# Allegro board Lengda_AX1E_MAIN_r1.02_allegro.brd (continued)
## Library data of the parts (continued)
PR4 PR14 PR15 PR36 PR39 PR41 PR47 PR73 R1 R6 R7 R17 R22 R26 R38 R42 R73 R92 R97 R98 R104 R106 R107 R109 R114 R122-R124 R127 R146-R149 R159 R169 R170 R176 R178 R180 R193 R196 R203 R222 R250 R266 R270 R277 R278 R283 R311 R312 R323 R324 R332 R333 R336 R341 R343 R346 R347 R358 R364 R366 R367 R376 R379 R395 R399 R409 R410 R438 R446 R506 R521 R537-R539 R543 R551 R556 R560 R561 R567 R568 R622 R624 R730 R732 R791 R796 R797 R800 R815 R860 R862 R865-R868 R874 R876 R917 R920 R926 R930 R932 = R: alternate symbols: (T:RC0603N;B:RC0603M)
PU3 = 8+1_RT9610CQW_0
Q1 Q2 Q4 Q11 Q18 Q40 = NMOS-GSD: alternate symbols: (T:SOT95P280-3N;B:SOT95P280-3M)
Q5 Q6 Q8 Q9 Q22 Q23 Q29 Q32 Q56 Q68 Q74 = PWR_N_MOSFET
Q7 Q10 Q15 Q30 Q31 Q69 Q71 Q76-Q81 Q83-Q86 Q88 = NMOS-GSD: alternate symbols: (T:SOT95P240-3N;B:SOT95P240-3M)
Q12 Q13 Q44 = NMOS-GSD_0
Q14 Q41 Q42 = NMOS-GSD
Q17 = PWR_P_MOSFET_1
Q19 Q27 = NMOS-GSD: signal model: NMOS-GSD_SOT95P240-3N_2N7002L_1_2N7002LT1
Q34 = 3_APM1110NU
Q36 Q72 = NPN-BEC+2R: alternate symbols: (T:SOT65P210-3N;B:SOT65P210-3M)
Q48 = FET_NMOS_0
Q49 = 2021390400
R4 R13 R14 R43 R45 R48 R56 R62 R71 R81 R87 R145 R150 R158 R161 R164 R166 R174 R182 R183 R190-R192 R197 R215 R218 R221 R223 R232 R234 R243-R245 R263 R264 R273-R275 R281 R331 R337 R362 R363 R371 R380 R385 R386 R421 R422 R426 R439 R462 R465 R478 R482 R485 R490 R492 R493 R501-R504 R509-R511 R514-R516 R522 R525 R526 R535 R542 R545 R572 R578-R580 R584-R587 R609 R610 R788-R790 R793 R795 R802 R803 R811 R816 R828 R833 R834 R877-R881 R883 R884 R886 R887 R890 R891 R893 R901 R902 R910 R918 R927 R928 R1392 = R_0
R11 R24 R126 R130 R319 R320 R334 R344 R368 R394 R406 R432 = R: signal model: R_RC0402N_0_0
R84 = R: signal model: R_RC0402N_10_10
R201 = R: signal model: R_0_RC0402N_0_0
R261 = R: alternate symbols: (T:RC1206N;B:RC1206M)
R314 R315 R448 R450-R457 R477 R479 R483 R484 R489 = R: signal model: R_RC0603N_0_0
R407 = R: signal model: R_RC0402N_22_22
R428-R431 R480 R481 R488 R491 = R: signal model: R_RC0603N_0_F_0_F
R449 = R_0: signal model: R_RC0603N_0_0
R463 R464 = R_0: signal model: R_0_RC0402N_0_0
R494-R500 R505 = R_0: signal model: R_0_RC0603N_0_0
R573 R574 = R: alternate symbols: (T:RC0805N;B:RC0805M)
R1388 = R_4
SW1 = SW-2+2
TP1 TP3 TP6-TP11 TP14 TP15 TP18 TP26-TP59 TP63 TP65 TP66 TP69-TP73 = TP
TP12 TP13 TP16 TP17 TP19 TP20 TP22 TP23 = PAD_1: room: CPU
TP21 TP24 TP25 = TP#2: room: TEST_POINT
U1 = 1526_ICLU_LP5366
U2 = 20+1_RT8231AB
U3 = 40+1_RT3613EB
U4 U14 = 5_APL3512
U5 U10 U18 U23 U32 U35 U40 U54 U56 U57 = 5_SN74LVC1G08DCKR
U6 = 20+1_RT6543A
U7 U20 U24 = 12_RT6228XGQUF
U9 = 128_IT5570_2
U11 U22 U27 U29 U41 = 5_APL3511
U13 U50 = 5_SN74LVC1G07DCK
U15 U16 U21 U39 U55 = 8+1_TPS22965
U25 = 48+1_ALC256
U30 = 32+1_RTL8111H
U31 = 24_EG24A005S
U33 = 5_SN74AHC1G09DCK
U34 = 5_SN74LVC1G06DCK
U36 = 8_MX25L4005AMC-12G
U36_S U49_1 = SPI_FLASH_3: Tolerance: #TOL; User Part Number: HAMP; room: EC
U37 = 16+1_APW7228BRI
U38 = 3_APL3517
U42 = 56+1_PS8625QFN56G
U43 U44 = 8_AT24C02A
U49 = 8_W25Q64FV
U51 = 10+1_APW8804QB_0
U52 = APL591X_1
UC1 = C: alternate symbols: (T:CC0805N;B:CC0805M)
X1 X2 = OSC-4_7
X4 = CRYSTAL

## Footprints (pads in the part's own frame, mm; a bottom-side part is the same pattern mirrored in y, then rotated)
BGA91P35X99_1526N
  round 0.356 smd: A3(10.767,-24.365) A48(-11.405,-24.365) A49(-11.865,-23.905) B2(11.309,-23.816) C1(11.865,-23.255) DW1(11.865,23.905) DW2(11.405,24.365) DW48(-11.405,24.365) DW49(-11.865,23.905)
  round 0.33 smd: A4(10.117,-24.365) A47(-10.755,-24.365) B3(10.666,-23.723) B48(-11.237,-23.737) C2(11.22,-23.172) C49(-11.865,-23.255) D1(11.865,-22.605) DE12(6.31,17.032) DE13(5.48,17.032) DE15(4.65,17.032) DE17(3.82,17.032) DE18(2.99,17.032) DE20(2.16,17.032) DE22(1.33,17.032) DE23(0.5,17.032) DE26(-0.33,17.032) DE28(-1.16,17.032) DE29(-1.99,17.032) DE31(-2.82,17.032) DE33(-3.65,17.032) DF12(6.31,17.682) DF13(5.48,17.682) DF15(4.65,17.682) DF17(3.82,17.682) DF18(2.99,17.682) DF20(2.16,17.682) DF22(1.33,17.682) DF23(0.5,17.682) DF26(-0.33,17.682) DF28(-1.16,17.682) DF29(-1.99,17.682) DF31(-2.82,17.682) DF33(-3.65,17.682) DG12(6.31,18.332) DG13(5.48,18.332) DG15(4.65,18.332) DG17(3.82,18.332) DG18(2.99,18.332) DG20(2.16,18.332) DG22(1.33,18.332) DG23(0.5,18.332) DG26(-0.33,18.332) DG28(-1.16,18.332) DG29(-1.99,18.332) DG31(-2.82,18.332) DG33(-3.65,18.332) DU1(11.865,23.255) DU49(-11.865,23.255) DV2(11.237,23.737) DV48(-11.237,23.737) DW3(10.755,24.365) DW47(-10.755,24.365)
  round 0.305 smd: A5(9.467,-24.365) A7(8.658,-24.365) A33(-3.593,-24.365) A43(-8.707,-24.365) A44(-9.455,-24.365) A46(-10.105,-24.365) AA12(6.127,-14.312) AA35(-4.855,-14.311) AA37(-5.778,-14.311) AA45(-9.59,-14.246) AA47(-10.861,-14.246) AB3(10.893,-13.923) AB5(9.905,-13.923) AB6(9.189,-13.855) AB7(8.539,-13.855) AB9(7.889,-13.855) AB10(7.239,-13.855) AB11(6.589,-13.855) AB13(5.665,-13.855) AB34(-4.393,-13.853) AB36(-5.316,-13.853) AB38(-6.24,-13.853) AB39(-6.89,-13.853) AB41(-7.54,-13.853) AB42(-8.19,-13.853) AB43(-8.84,-13.853) AB45(-9.915,-13.626) AB47(-10.565,-13.626) AC3(10.565,-13.249) AC5(9.915,-13.249) AC12(6.127,-13.397) AC35(-4.855,-13.396) AC37(-5.778,-13.396) AC45(-9.59,-12.995) AC46(-10.241,-12.995) AD3(10.89,-12.686) AD4(10.24,-12.686) AD6(9.189,-12.94) AD7(8.539,-12.94) AD9(7.889,-12.94) AD10(7.239,-12.94) AD11(6.589,-12.94) AD34(-4.393,-12.938) AD35(-4.855,-12.481) AD36(-5.316,-12.938) AD37(-5.778,-12.481) AD38(-6.24,-12.938) AD39(-6.89,-12.938) AD41(-7.54,-12.938) AD42(-8.19,-12.938) AD43(-8.84,-12.938) AE3(10.565,-12.123) AE5(9.915,-12.123) AE6(9.189,-12.025) AE7(8.539,-12.025) AE9(7.889,-12.025) AE11(6.965,-12.025) AE36(-5.316,-12.023) AE38(-6.24,-12.023) AE39(-6.89,-12.023) AE41(-7.54,-12.023) AE42(-8.19,-12.023) AE43(-8.84,-12.023) AE45(-9.915,-12.364) AE47(-10.565,-12.364) AF10(7.427,-11.567) AF37(-5.778,-11.566) AF45(-9.59,-11.744) AF47(-10.861,-11.744) AG3(10.893,-11.449) AG5(9.905,-11.449) AG6(9.189,-11.11) AG7(8.539,-11.11) AG9(7.889,-11.11) AG11(6.965,-11.11) AG36(-5.316,-11.108) AG38(-6.24,-11.108) AG39(-6.89,-11.108) AG41(-7.54,-11.108) AG42(-8.19,-11.108) AG43(-8.84,-11.108) AG45(-9.915,-11.124) AG47(-10.565,-11.124) AH10(7.427,-10.652) AH37(-5.778,-10.651) AH45(-9.59,-10.493) AH46(-10.241,-10.493) AJ3(10.489,-10.195) AJ5(9.839,-10.195) AJ6(9.189,-10.195) AJ7(8.539,-10.195) AJ9(7.889,-10.195) AJ11(6.965,-10.195) AJ36(-5.316,-10.193) AJ38(-6.24,-10.193) AJ39(-6.89,-10.193) AJ41(-7.54,-10.193) AJ42(-8.19,-10.193) AJ43(-8.84,-10.193) AK10(7.427,-9.737) AK37(-5.778,-9.736) AK45(-9.915,-9.862) AK47(-10.565,-9.862) AL3(10.489,-9.28) AL5(9.839,-9.28) AL6(9.189,-9.28) AL7(8.539,-9.28) AL9(7.889,-9.28) AL11(6.965,-9.28) AL36(-5.316,-9.278) AL38(-6.24,-9.278) AL39(-6.89,-9.278) AL41(-7.54,-9.278) AL42(-8.19,-9.278) AL43(-8.84,-9.278) AL45(-9.59,-9.242) AL47(-10.861,-9.242) AM10(7.427,-8.822) AM37(-5.778,-8.821) AM45(-9.915,-8.622) AM47(-10.565,-8.622) AN3(10.489,-8.365) AN5(9.839,-8.365) AN6(9.189,-8.365) AN7(8.539,-8.365) AN9(7.889,-8.365) AN11(6.965,-8.365) AN36(-5.316,-8.363) AN38(-6.24,-8.363) AN39(-6.89,-8.363) AN41(-7.54,-8.363) AN42(-8.19,-8.363) AN43(-8.84,-8.363) AN45(-9.59,-7.991) AN46(-10.241,-7.991) AP10(7.427,-7.907) AP37(-5.778,-7.906) AR3(10.489,-7.45) AR5(9.839,-7.45) AR6(9.189,-7.45) AR7(8.539,-7.45) AR9(7.889,-7.45) AR10(7.427,-6.992) AR11(6.965,-7.45) AR36(-5.316,-7.448) AR37(-5.778,-6.991) AR38(-6.24,-7.448) AR39(-6.89,-7.448) AR41(-7.54,-7.448) AR42(-8.19,-7.448) AR43(-8.84,-7.448) AR45(-9.915,-7.36) AR47(-10.565,-7.36) AT3(10.489,-6.535) AT5(9.839,-6.535) AT6(9.189,-6.535) AT7(8.539,-6.535) AT9(7.889,-6.535) AT11(6.965,-6.535) AT36(-5.316,-6.533) AT38(-6.24,-6.533) AT39(-6.89,-6.533) AT41(-7.54,-6.533) AT42(-8.19,-6.533) AT43(-8.84,-6.533) AT45(-9.59,-6.74) AT47(-10.861,-6.74) AU10(7.427,-6.077) AU37(-5.778,-6.076) AU45(-9.915,-6.12) AU47(-10.565,-6.12) AV3(10.489,-5.62) AV5(9.839,-5.62) AV6(9.189,-5.62) AV7(8.539,-5.62) AV9(7.889,-5.62) AV11(6.965,-5.62) AV36(-5.316,-5.618) AV38(-6.24,-5.618) AV39(-6.89,-5.618) AV41(-7.54,-5.618) AV42(-8.19,-5.618) AV43(-8.84,-5.618) AV45(-9.59,-5.489) AV46(-10.241,-5.489) AW10(7.427,-5.162) AW37(-5.778,-5.161) AY3(10.489,-4.705) AY5(9.839,-4.705) AY6(9.189,-4.705) AY7(8.539,-4.705) AY9(7.889,-4.705) AY11(6.965,-4.705) AY36(-5.316,-4.703) AY38(-6.24,-4.703) AY39(-6.89,-4.703) AY41(-7.54,-4.703) AY42(-8.19,-4.703) AY43(-8.84,-4.703) AY45(-9.915,-4.858) AY47(-10.565,-4.858) B4(10.016,-23.723) B7(8.658,-23.715) B33(-3.593,-23.715) B43(-8.707,-23.715) B45(-9.956,-23.577) B47(-10.587,-23.737) BA10(7.427,-4.247) BA37(-5.778,-4.246) BA45(-9.59,-4.238) BA47(-10.861,-4.238) BB3(10.489,-3.79) BB5(9.839,-3.79) BB6(9.189,-3.79) BB7(8.539,-3.79) BB9(7.889,-3.79) BB11(6.965,-3.79) BB36(-5.316,-3.788) BB38(-6.24,-3.788) BB39(-6.89,-3.788) BB41(-7.54,-3.788) BB42(-8.19,-3.788) BB43(-8.84,-3.788) BB45(-9.915,-3.618) BB47(-10.565,-3.618) BC10(7.427,-3.332) BC37(-5.778,-3.331) BD3(10.489,-2.875) BD5(9.839,-2.875) BD6(9.189,-2.875) BD7(8.539,-2.875) BD9(7.889,-2.875) BD11(6.965,-2.875) BD36(-5.316,-2.873) BD38(-6.24,-2.873) BD39(-6.89,-2.873) BD41(-7.54,-2.873) BD42(-8.19,-2.873) BD43(-8.84,-2.873) BD45(-9.59,-2.987) BD46(-10.241,-2.987) BE10(7.427,-2.417) BE37(-5.778,-2.416) BE45(-9.915,-2.356) BE47(-10.565,-2.356) BF3(10.489,-1.96) BF5(9.839,-1.96) BF6(9.189,-1.96) BF7(8.539,-1.96) BF9(7.889,-1.96) BF10(7.427,-1.502) BF11(6.965,-1.96) BF36(-5.316,-1.958) BF37(-5.778,-1.501) BF38(-6.24,-1.958) BF39(-6.89,-1.958) BF41(-7.54,-1.958) BF42(-8.19,-1.958) BF43(-8.84,-1.958) BF45(-9.59,-1.736) BF47(-10.861,-1.736) BG3(10.489,-1.045) BG5(9.839,-1.045) BG6(9.189,-1.045) BG7(8.539,-1.045) BG9(7.889,-1.045) BG11(6.965,-1.045) BG36(-5.316,-1.043) BG38(-6.24,-1.043) BG39(-6.89,-1.043) BG41(-7.54,-1.043) BG42(-8.19,-1.043) BG43(-8.84,-1.043) BG45(-9.915,-1.116) BG47(-10.565,-1.116) BH10(7.427,-0.587) BH37(-5.778,-0.586) BJ3(10.489,-0.13) BJ5(9.839,-0.13) BJ6(9.189,-0.13) BJ7(8.539,-0.13) BJ9(7.889,-0.13) BJ11(6.965,-0.13) BJ36(-5.316,-0.128) BJ38(-6.24,-0.128) BJ39(-6.89,-0.128) BJ41(-7.54,-0.128) BJ42(-8.19,-0.128) BJ43(-8.84,-0.128) BJ45(-9.59,-0.485) BJ46(-10.241,-0.485) BL10(7.427,0.328) BL37(-5.778,0.33) BL45(-9.915,0.146) BL47(-10.565,0.146) BM3(10.489,0.786) BM5(9.839,0.786) BM6(9.189,0.786) BM7(8.539,0.786) BM9(7.889,0.786) BM11(6.965,0.786) BM36(-5.316,0.787) BM38(-6.24,0.787) BM39(-6.89,0.787) BM41(-7.54,0.787) BM42(-8.19,0.787) BM43(-8.84,0.787) BM45(-9.59,0.766) BM47(-10.861,0.766) BN10(7.427,1.243) BN37(-5.778,1.245) BN45(-9.915,1.386) BN47(-10.565,1.386) BP3(10.489,1.701) BP5(9.839,1.701) BP6(9.189,1.701) BP7(8.539,1.701) BP9(7.889,1.701) BP11(6.965,1.701) BP36(-5.316,1.702) BP38(-6.24,1.702) BP39(-6.89,1.702) BP41(-7.54,1.702) BP42(-8.19,1.702) BP43(-8.84,1.702) BR10(7.427,2.158) BR37(-5.778,2.16) BR45(-9.59,2.017) BR46(-10.241,2.017) BT3(10.489,2.616) BT5(9.839,2.616) BT6(9.189,2.616) BT7(8.539,2.616) BT9(7.889,2.616) BT11(6.965,2.616) BT36(-5.316,2.617) BT38(-6.24,2.617) BT39(-6.89,2.617) BT41(-7.54,2.617) BT42(-8.19,2.617) BT43(-8.84,2.617) BT45(-9.915,2.648) BT47(-10.565,2.648) BU10(7.427,3.073) BU37(-5.778,3.075) BU45(-9.59,3.268) BU47(-10.861,3.268) BV3(10.489,3.531) BV5(9.839,3.531) BV6(9.189,3.531) BV7(8.539,3.531) BV9(7.889,3.531) BV11(6.965,3.531) BV36(-5.316,3.532) BV38(-6.24,3.532) BV39(-6.89,3.532) BV41(-7.54,3.532) BV42(-8.19,3.532) BV43(-8.84,3.532) BV45(-9.915,3.888) BV47(-10.565,3.888) BW3(10.489,4.446) BW5(9.839,4.446) BW6(9.189,4.446) BW7(8.539,4.446) BW9(7.889,4.446) BW10(7.427,3.988) BW11(6.965,4.446) BW36(-5.316,4.447) BW37(-5.778,3.99) BW38(-6.24,4.447) BW39(-6.89,4.447) BW41(-7.54,4.447) BW42(-8.19,4.447) BW43(-8.84,4.447) BY10(7.427,4.903) BY37(-5.778,4.905) BY45(-9.59,4.519) BY46(-10.241,4.519) C3(10.577,-23.079) C5(9.927,-23.079) C6(9.332,-23.393) C7(8.658,-23.065) C8(8.095,-23.39) C9(7.532,-23.065) C11(6.858,-23.393) C12(6.184,-23.065) C13(5.621,-23.39) C14(5.058,-23.065) C16(4.384,-23.393) C33(-3.593,-23.065) C34(-4.176,-23.361) C35(-4.795,-23.065) C38(-6.077,-23.065) C39(-6.73,-23.361) C40(-7.383,-23.065) C43(-8.707,-23.065) C44(-9.336,-23.359) C47(-10.479,-23.087) C48(-11.234,-23.087) CA3(10.489,5.361) CA5(9.839,5.361) CA6(9.189,5.361) CA7(8.539,5.361) CA9(7.889,5.361) CA11(6.965,5.361) CA36(-5.316,5.362) CA38(-6.24,5.362) CA39(-6.89,5.362) CA41(-7.54,5.362) CA42(-8.19,5.362) CA43(-8.84,5.362) CA45(-9.915,5.15) CA47(-10.565,5.15) CB10(7.427,5.818) CB37(-5.778,5.82) CB45(-9.59,5.77) CB47(-10.861,5.77) CC3(10.893,6.149) CC5(9.905,6.149) CC6(9.189,6.276) CC7(8.539,6.276) CC9(7.889,6.276) CC11(6.965,6.276) CC36(-5.316,6.277) CC38(-6.24,6.277) CC39(-6.89,6.277) CC41(-7.54,6.277) CC42(-8.19,6.277) CC43(-8.84,6.277) CC45(-9.915,6.39) CC47(-10.565,6.39) CD3(10.565,6.823) CD5(9.915,6.823) CD10(7.427,6.733) CE3(10.89,7.386) CE4(10.24,7.386) CE6(9.189,7.191) CE7(8.539,7.191) CE9(7.889,7.191) CE11(6.965,7.191) CE34(-4.29,7.192) CE35(-4.94,7.192) CE37(-5.59,7.192) CE38(-6.24,7.192) CE39(-6.89,7.192) CE41(-7.54,7.192) CE42(-8.19,7.192) CE43(-8.84,7.192) CE45(-9.59,7.021) CE46(-10.241,7.021) CF3(10.565,7.949) CF5(9.915,7.949) CF10(7.427,7.648) CF33(-3.828,7.65) CF45(-9.915,7.652) CF47(-10.565,7.652) CG6(9.189,8.106) CG7(8.539,8.106) CG9(7.889,8.106) CG11(6.965,8.106) CG32(-3.366,8.107) CG34(-4.29,8.107) CG35(-4.94,8.107) CG37(-5.59,8.107) CG38(-6.24,8.107) CG39(-6.89,8.107) CG41(-7.54,8.107) CG42(-8.19,8.107) CG43(-8.84,8.107) CG45(-9.59,8.272) CG47(-10.861,8.272) CH3(10.893,8.623) CH5(9.905,8.623) CH10(7.427,8.563) CH33(-3.828,8.689) CH45(-9.915,8.892) CH47(-10.565,8.892) CJ3(10.565,9.297) CJ5(9.915,9.297) CJ6(9.189,9.021) CJ7(8.539,9.021) CJ9(7.889,9.021) CJ11(6.965,9.021) CJ32(-3.366,9.272) CJ34(-4.29,9.272) CJ35(-4.94,9.272) CJ37(-5.59,9.272) CJ38(-6.24,9.272) CJ39(-6.89,9.272) CJ41(-7.54,9.272) CJ42(-8.19,9.272) CJ43(-8.84,9.272) CK3(10.89,9.86) CK4(10.24,9.86) CK6(9.189,9.936) CK7(8.539,9.936) CK9(7.889,9.936) CK10(7.427,9.478) CK11(6.965,9.936) CK33(-3.828,9.73) CK45(-9.59,9.523) CK46(-10.241,9.523) CL3(10.565,10.423) CL5(9.915,10.423) CL10(7.427,10.393) CL32(-3.366,10.187) CL34(-4.29,10.187) CL35(-4.94,10.187) CL37(-5.59,10.187) CL38(-6.24,10.187) CL39(-6.89,10.187) CL41(-7.54,10.187) CL42(-8.19,10.187) CL43(-8.84,10.187) CL45(-9.915,10.154) CL47(-10.565,10.154) CM6(9.189,10.851) CM7(8.539,10.851) CM9(7.889,10.851) CM11(6.965,10.851) CM33(-3.828,10.645) CM45(-9.59,10.774) CM47(-10.861,10.774) CN3(10.893,11.097) CN5(9.905,11.097) CN10(7.427,11.308) CN32(-3.366,11.102) CN34(-4.29,11.102) CN35(-4.94,11.102) CN37(-5.59,11.102) CN38(-6.24,11.102) CN39(-6.89,11.102) CN41(-7.54,11.102) CN42(-8.19,11.102) CN43(-8.84,11.102) CN45(-9.915,11.394) CN47(-10.565,11.394) CP3(10.565,11.771) CP5(9.915,11.771) CP6(9.189,11.766) CP7(8.539,11.766) CP9(7.889,11.766) CP11(6.965,11.766) CP33(-3.828,11.56) CR3(10.89,12.334) CR4(10.24,12.334) CR10(7.427,12.223) CR32(-3.366,12.017) CR34(-4.29,12.017) CR35(-4.94,12.017) CR37(-5.59,12.017) CR38(-6.24,12.017) CR39(-6.89,12.017) CR41(-7.54,12.017) CR42(-8.19,12.017) CR43(-8.84,12.017) CR45(-9.59,12.025) CR46(-10.241,12.025) CT3(10.565,12.897) CT5(9.915,12.897) CT6(9.189,12.681) CT7(8.539,12.681) CT9(7.889,12.681) CT11(6.965,12.681) CT32(-3.366,12.932) CT33(-3.828,12.475) CT34(-4.29,12.932) CT35(-4.94,12.932) CT37(-5.59,12.932) CT38(-6.24,12.932) CT39(-6.89,12.932) CT41(-7.54,12.932) CT42(-8.19,12.932) CT43(-8.84,12.932) CT45(-9.915,12.656) CT47(-10.565,12.656) CU10(7.427,13.138) CU33(-3.828,13.39) CU45(-9.59,13.276) CU47(-10.861,13.276) CV3(10.893,13.571) CV5(9.905,13.571) CV6(9.189,13.596) CV7(8.539,13.596) CV9(7.889,13.596) CV11(6.965,13.596) CV32(-3.366,13.847) CV34(-4.29,13.847) CV35(-4.94,13.847) CV37(-5.59,13.847) CV38(-6.24,13.847) CV39(-6.89,13.847) CV41(-7.54,13.847) CV42(-8.19,13.847) CV43(-8.84,13.847) CV45(-9.915,13.896) CV47(-10.565,13.896) CW3(10.565,14.245) CW5(9.915,14.245) CW10(7.427,14.053) CW33(-3.828,14.305) CY3(10.89,14.808) CY4(10.24,14.808) CY6(9.189,14.511) CY7(8.539,14.511) CY9(7.889,14.511) CY11(6.965,14.511) CY32(-3.366,14.762) CY34(-4.29,14.762) CY35(-4.94,14.762) CY37(-5.59,14.762) CY38(-6.24,14.762) CY39(-6.89,14.762) CY41(-7.54,14.762) CY42(-8.19,14.762) CY43(-8.84,14.762) CY45(-9.59,14.527) CY46(-10.241,14.527) D2(11.22,-22.522) D4(10.381,-22.459) D7(8.658,-22.415) D8(8.095,-22.74) D9(7.532,-22.415) D12(6.184,-22.415) D13(5.621,-22.74) D14(5.058,-22.415) D33(-3.593,-22.415) D35(-4.795,-22.415) D36(-5.424,-22.741) D38(-6.077,-22.415) D40(-7.383,-22.415) D42(-8.036,-22.741) D43(-8.707,-22.415) D44(-9.354,-22.492) D47(-10.866,-22.545) D49(-11.865,-22.605) DA3(10.565,15.371) DA5(9.915,15.371) DA6(9.189,15.426) DA7(8.539,15.426) DA9(7.889,15.426) DA10(7.427,14.968) DA11(6.965,15.426) DA33(-3.828,15.22) DA45(-9.915,15.158) DA47(-10.565,15.158) DB10(7.427,15.883) DB32(-3.366,15.677) DB34(-4.29,15.677) DB35(-4.94,15.677) DB37(-5.59,15.677) DB38(-6.24,15.677) DB39(-6.89,15.677) DB41(-7.54,15.677) DB42(-8.19,15.677) DB43(-8.84,15.677) DB45(-9.59,15.778) DB47(-10.861,15.778) DC3(10.893,16.045) DC5(9.905,16.045) DC6(9.189,16.341) DC7(8.539,16.341) DC9(7.889,16.341) DC11(6.965,16.341) DC33(-3.828,16.135) DC45(-9.915,16.398) DC47(-10.565,16.398) DD3(10.565,16.719) DD5(9.915,16.719) DD34(-4.29,16.592) DD35(-4.94,16.592) DD37(-5.59,16.592) DD38(-6.24,16.592) DD39(-6.89,16.592) DD41(-7.54,16.592) DD42(-8.19,16.592) DD43(-8.84,16.592) DE3(10.89,17.282) DE4(10.24,17.282) DE6(9.189,17.256) DE7(8.539,17.256) DE9(7.889,17.256) DE10(7.239,17.256) DE45(-9.59,17.029) DE46(-10.241,17.029) DF3(10.565,17.845) DF5(9.915,17.845) DF34(-4.29,17.507) DF35(-4.94,17.507) DF37(-5.59,17.507) DF38(-6.24,17.507) DF39(-6.89,17.507) DF41(-7.54,17.507) DF42(-8.19,17.507) DF43(-8.84,17.507) DF45(-9.915,17.66) DF47(-10.565,17.66) DG6(9.189,18.171) DG7(8.539,18.171) DG9(7.889,18.171) DG10(7.239,18.171) DG34(-4.476,18.332) DG36(-5.391,18.332) DG38(-6.306,18.332) DG40(-7.221,18.332) DG42(-8.136,18.332) DG44(-9.051,18.332) DG47(-10.861,18.288) DH3(10.893,18.519) DH5(9.905,18.519) DH45(-9.915,18.871) DH47(-10.565,18.871) DJ3(10.565,19.193) DJ5(9.915,19.193) DJ6(9.249,18.982) DJ8(8.334,18.982) DJ10(7.419,18.982) DJ11(6.504,18.982) DJ13(5.589,18.982) DJ15(4.674,18.982) DJ17(3.759,18.982) DJ19(2.844,18.982) DJ21(1.929,18.982) DJ22(1.014,18.982) DJ24(0.099,18.982) DJ27(-0.816,18.982) DJ29(-1.731,18.982) DJ31(-2.646,18.982) DJ33(-3.561,18.982) DJ34(-4.476,18.982) DJ36(-5.391,18.982) DJ38(-6.306,18.982) DJ40(-7.221,18.982) DJ42(-8.136,18.982) DJ44(-9.051,18.982) DK3(10.89,19.756) DK4(10.24,19.756) DK6(9.249,19.632) DK8(8.334,19.632) DK10(7.419,19.632) DK11(6.504,19.632) DK13(5.589,19.632) DK15(4.674,19.632) DK17(3.759,19.632) DK19(2.844,19.632) DK21(1.929,19.632) DK22(1.014,19.632) DK24(0.099,19.632) DK27(-0.816,19.632) DK29(-1.731,19.632) DK31(-2.646,19.632) DK33(-3.561,19.632) DK34(-4.476,19.632) DK36(-5.391,19.632) DK38(-6.306,19.632) DK40(-7.221,19.632) DK42(-8.136,19.632) DK44(-9.051,19.632) DK46(-10.24,19.524) DL3(10.565,20.319) DL5(9.915,20.319) DL6(9.249,20.282) DL8(8.334,20.282) DL10(7.419,20.282) DL11(6.504,20.282) DL13(5.589,20.282) DL15(4.674,20.282) DL17(3.759,20.282) DL19(2.844,20.282) DL21(1.929,20.282) DL22(1.014,20.282) DL24(0.099,20.282) DL27(-0.816,20.282) DL29(-1.731,20.282) DL31(-2.646,20.282) DL33(-3.561,20.282) DL34(-4.476,20.282) DL36(-5.391,20.282) DL38(-6.306,20.282) DL40(-7.221,20.282) DL42(-8.136,20.282) DL44(-9.051,20.282) DL45(-9.915,20.177) DL47(-10.565,20.177) DN3(10.893,20.993) DN5(9.905,20.993) DN6(9.249,20.932) DN8(8.334,20.932) DN10(7.419,20.932) DN11(6.504,20.932) DN13(5.589,20.932) DN15(4.674,20.932) DN17(3.759,20.932) DN19(2.844,20.932) DN21(1.929,20.932) DN22(1.014,20.932) DN24(0.099,20.932) DN27(-0.816,20.932) DN29(-1.731,20.932) DN31(-2.646,20.932) DN33(-3.561,20.932) DN34(-4.476,20.932) DN36(-5.391,20.932) DN38(-6.306,20.932) DN40(-7.221,20.932) DN42(-8.136,20.932) DN44(-9.051,20.932) DN47(-10.565,21.305) DP1(11.865,21.667) DP3(10.565,21.667) DP5(9.915,21.667) DP6(9.249,21.582) DP8(8.334,21.582) DP10(7.419,21.582) DP11(6.504,21.582) DP13(5.589,21.582) DP15(4.674,21.582) DP17(3.759,21.582) DP19(2.844,21.582) DP21(1.929,21.582) DP22(1.014,21.582) DP24(0.099,21.582) DP27(-0.816,21.582) DP29(-1.731,21.582) DP31(-2.646,21.582) DP33(-3.561,21.582) DP34(-4.476,21.582) DP36(-5.391,21.582) DP38(-6.306,21.582) DP40(-7.221,21.582) DP42(-8.136,21.582) DP44(-9.051,21.582) DP45(-9.915,21.629) DR5(9.948,22.316) DR47(-10.565,21.955) DR48(-11.215,21.955) DR49(-11.865,21.955) DT1(11.865,22.605) DT2(11.237,22.437) DT3(10.587,22.437) DT6(9.306,22.415) DT7(8.67,22.74) DT8(8.017,22.415) DT10(7.36,22.415) DT11(6.703,22.415) DT12(6.05,22.74) DT14(5.397,22.415) DT15(4.74,22.415) DT16(4.083,22.415) DT18(3.43,22.74) DT19(2.777,22.415) DT20(2.12,22.415) DT22(1.463,22.415) DT23(0.81,22.74) DT24(0.157,22.415) DT27(-0.5,22.415) DT28(-1.157,22.415) DT29(-1.81,22.74) DT30(-2.463,22.415) DT32(-3.12,22.415) DT33(-3.777,22.415) DT34(-4.43,22.74) DT36(-5.083,22.415) DT37(-5.74,22.415) DT38(-6.397,22.415) DT40(-7.05,22.74) DT41(-7.703,22.415) DT42(-8.36,22.415) DT44(-9.026,22.416) DT45(-9.676,22.48) DT47(-10.906,22.527) DT49(-11.865,22.605) DU2(11.237,23.087) DU3(10.587,23.087) DU6(9.323,23.065) DU10(7.36,23.39) DU15(4.74,23.39) DU20(2.12,23.39) DU27(-0.5,23.39) DU32(-3.12,23.39) DU37(-5.74,23.39) DU42(-8.36,23.39) DU44(-9.026,23.066) DU45(-9.676,23.13) DU47(-10.566,23.084) DU48(-11.236,23.087) DV3(10.587,23.737) DV4(10.023,23.41) DV6(9.426,23.715) DV44(-9.026,23.716) DV45(-9.936,23.733) DV47(-10.586,23.734) DW4(10.105,24.365) DW6(9.426,24.365) DW44(-9.026,24.366) DW46(-10.105,24.365) E1(11.865,-21.955) E3(10.836,-21.994) E5(9.87,-22.002) E6(9.332,-22.4) E11(6.858,-22.4) E16(4.384,-22.4) E34(-4.176,-22.091) E36(-5.424,-22.091) E39(-6.73,-22.091) E42(-8.036,-22.091) E46(-10.226,-22.394) E48(-11.43,-22.101) F6(9.282,-21.697) F8(8.367,-21.697) F10(7.452,-21.697) F11(6.537,-21.697) F13(5.622,-21.697) F15(4.707,-21.697) F17(3.728,-21.765) F33(-3.593,-21.765) F45(-9.59,-21.874) F47(-10.809,-21.89) G1(11.542,-21.379) G3(10.893,-21.346) G5(9.905,-21.346) G6(9.282,-21.047) G8(8.367,-21.047) G10(7.452,-21.047) G11(6.537,-21.047) G13(5.622,-21.047) G15(4.707,-21.047) G17(3.728,-21.115) G33(-3.593,-21.115) G34(-4.404,-21.344) G36(-5.319,-21.344) G38(-6.24,-21.173) G39(-6.89,-21.173) G41(-7.54,-21.173) G42(-8.19,-21.173) G43(-8.84,-21.173) G45(-9.915,-21.259) G47(-10.565,-21.259) G48(-11.215,-21.314) G49(-11.865,-21.314) H1(11.865,-20.671) H3(10.565,-20.671) H5(9.915,-20.671) H17(3.728,-20.465) H33(-3.593,-20.465) H34(-4.404,-20.694) H36(-5.319,-20.694) H45(-9.59,-20.641) H46(-10.24,-20.641) J3(10.89,-20.108) J4(10.24,-20.108) J6(9.282,-20.397) J8(8.367,-20.397) J10(7.452,-20.397) J11(6.537,-20.397) J13(5.622,-20.397) J15(4.707,-20.397) J16(4.185,-20.003) J18(3.27,-20.003) J20(2.355,-20.003) J22(1.44,-20.003) J23(0.525,-20.003) J26(-0.39,-20.003) J28(-1.305,-20.003) J30(-2.22,-20.003) J32(-3.135,-20.003) J34(-4.404,-20.044) J36(-5.319,-20.044) J38(-6.24,-20.258) J39(-6.89,-20.258) J41(-7.54,-20.258) J42(-8.19,-20.258) J43(-8.84,-20.258) J45(-9.915,-19.988) J47(-10.565,-19.988) K3(10.565,-19.545) K5(9.915,-19.545) K6(9.282,-19.747) K8(8.367,-19.747) K10(7.452,-19.747) K11(6.537,-19.747) K13(5.622,-19.747) K15(4.643,-19.541) K17(3.728,-19.541) K19(2.813,-19.541) K21(1.898,-19.541) K23(0.983,-19.541) K24(0.068,-19.541) K27(-0.848,-19.541) K29(-1.763,-19.541) K31(-2.678,-19.541) K33(-3.593,-19.541) L6(9.282,-19.097) L8(8.367,-19.097) L10(7.452,-19.097) L11(6.537,-19.097) L13(5.622,-19.097) L34(-4.404,-19.394) L36(-5.319,-19.394) L38(-6.24,-19.343) L39(-6.89,-19.343) L41(-7.54,-19.343) L42(-8.19,-19.343) L43(-8.84,-19.343) L45(-9.59,-19.335) L47(-10.861,-19.335) M3(10.893,-18.871) M5(9.905,-18.871) M6(9.282,-18.447) M8(8.367,-18.447) M10(7.452,-18.447) M11(6.537,-18.447) M13(5.622,-18.447) M34(-4.404,-18.744) M36(-5.319,-18.744) M38(-6.24,-18.428) M39(-6.89,-18.428) M41(-7.54,-18.428) M42(-8.19,-18.428) M43(-8.84,-18.428) M45(-9.915,-18.682) M47(-10.565,-18.682) N3(10.565,-18.197) N5(9.915,-18.197) N34(-4.404,-18.094) N36(-5.319,-18.094) N45(-9.59,-18.029) N46(-10.24,-18.029) P3(10.89,-17.634) P4(10.24,-17.634) P6(9.282,-17.797) P8(8.367,-17.797) P10(7.452,-17.797) P11(6.537,-17.797) P13(5.622,-17.797) P38(-6.24,-17.513) P39(-6.89,-17.513) P41(-7.54,-17.513) P42(-8.19,-17.513) P43(-8.84,-17.513) R3(10.565,-17.071) R5(9.915,-17.071) R12(6.127,-17.057) R35(-4.855,-17.056) R37(-5.778,-17.056) R45(-9.915,-17.376) R47(-10.565,-17.376) T6(9.189,-16.6) T7(8.539,-16.6) T9(7.889,-16.6) T10(7.239,-16.6) T11(6.589,-16.6) T13(5.665,-16.6) T34(-4.393,-16.598) T36(-5.316,-16.598) T38(-6.24,-16.598) T39(-6.89,-16.598) T41(-7.54,-16.598) T42(-8.19,-16.598) T43(-8.84,-16.598) T45(-9.59,-16.748) T47(-10.861,-16.748) U3(10.893,-16.397) U5(9.905,-16.397) U12(6.127,-16.142) U35(-4.855,-16.141) U37(-5.778,-16.141) U45(-9.915,-16.128) U47(-10.565,-16.128) V3(10.565,-15.723) V5(9.915,-15.723) V6(9.189,-15.685) V7(8.539,-15.685) V9(7.889,-15.685) V10(7.239,-15.685) V11(6.589,-15.685) V13(5.665,-15.685) V34(-4.393,-15.683) V36(-5.316,-15.683) V38(-6.24,-15.683) V39(-6.89,-15.683) V41(-7.54,-15.683) V42(-8.19,-15.683) V43(-8.84,-15.683) V45(-9.59,-15.497) V46(-10.241,-15.497) W3(10.89,-15.16) W4(10.24,-15.16) W12(6.127,-15.227) W35(-4.855,-15.226) W37(-5.778,-15.226) Y3(10.565,-14.597) Y5(9.915,-14.597) Y6(9.189,-14.77) Y7(8.539,-14.77) Y9(7.889,-14.77) Y10(7.239,-14.77) Y11(6.589,-14.77) Y13(5.665,-14.77) Y34(-4.393,-14.768) Y36(-5.316,-14.768) Y38(-6.24,-14.768) Y39(-6.89,-14.768) Y41(-7.54,-14.768) Y42(-8.19,-14.768) Y43(-8.84,-14.768) Y45(-9.915,-14.866) Y47(-10.565,-14.866)
  oval 0.254x0.33 smd: A9(7.532,-24.365) A11(6.858,-24.043) A12(6.184,-24.365) A14(5.058,-24.365) A16(4.384,-24.043) A36(-5.424,-24.041) A38(-6.077,-24.365) A39(-6.73,-24.041) A40(-7.383,-24.365) A42(-8.036,-24.041) B9(7.532,-23.715) B12(6.184,-23.715) B14(5.058,-23.715) B38(-6.077,-23.715) B40(-7.383,-23.715) C36(-5.424,-23.391) C42(-8.036,-23.391) DU7(8.67,23.39) DU8(8.017,23.065) DU11(6.703,23.065) DU12(6.05,23.39) DU14(5.397,23.065) DU16(4.083,23.065) DU18(3.43,23.39) DU19(2.777,23.065) DU22(1.463,23.065) DU23(0.81,23.39) DU24(0.157,23.065) DU28(-1.157,23.065) DU29(-1.81,23.39) DU30(-2.463,23.065) DU33(-3.777,23.065) DU34(-4.43,23.39) DU36(-5.083,23.065) DU38(-6.397,23.065) DU40(-7.05,23.39) DU41(-7.703,23.065) DV8(8.017,23.715) DV11(6.703,23.715) DV14(5.397,23.715) DV16(4.083,23.715) DV19(2.777,23.715) DV22(1.463,23.715) DV24(0.157,23.715) DV28(-1.157,23.715) DV30(-2.463,23.715) DV33(-3.777,23.715) DV36(-5.083,23.715) DV38(-6.397,23.715) DV41(-7.703,23.715) DW7(8.67,24.04) DW8(8.017,24.365) DW10(7.36,24.04) DW11(6.703,24.365) DW12(6.05,24.04) DW14(5.397,24.365) DW15(4.74,24.04) DW16(4.083,24.365) DW18(3.43,24.04) DW19(2.777,24.365) DW20(2.12,24.04) DW22(1.463,24.365) DW23(0.81,24.04) DW24(0.157,24.365) DW27(-0.5,24.04) DW28(-1.157,24.365) DW29(-1.81,24.04) DW30(-2.463,24.365) DW32(-3.12,24.04) DW33(-3.777,24.365) DW34(-4.43,24.04) DW36(-5.083,24.365) DW37(-5.74,24.04) DW38(-6.397,24.365) DW40(-7.05,24.04) DW41(-7.703,24.365) DW42(-8.36,24.04)
  round 0.406 smd: A17(3.728,-24.365) A19(2.813,-24.365) A21(1.898,-24.365) A23(0.983,-24.365) A24(0.068,-24.365) A27(-0.848,-24.365) A29(-1.763,-24.365) A31(-2.678,-24.365) B17(3.728,-23.715) B19(2.813,-23.715) B21(1.898,-23.715) B23(0.983,-23.715) B24(0.068,-23.715) B27(-0.848,-23.715) B29(-1.763,-23.715) B31(-2.678,-23.715) C17(3.728,-23.065) C19(2.813,-23.065) C21(1.898,-23.065) C23(0.983,-23.065) C24(0.068,-23.065) C27(-0.848,-23.065) C29(-1.763,-23.065) C31(-2.678,-23.065) D17(3.728,-22.415) D19(2.813,-22.415) D21(1.898,-22.415) D23(0.983,-22.415) D24(0.068,-22.415) D27(-0.848,-22.415) D29(-1.763,-22.415) D31(-2.678,-22.415) F19(2.813,-21.765) F21(1.898,-21.765) F23(0.983,-21.765) F24(0.068,-21.765) F27(-0.848,-21.765) F29(-1.763,-21.765) F31(-2.678,-21.765) G19(2.813,-21.115) G21(1.898,-21.115) G23(0.983,-21.115) G24(0.068,-21.115) G27(-0.848,-21.115) G29(-1.763,-21.115) G31(-2.678,-21.115) H19(2.813,-20.465) H21(1.898,-20.465) H23(0.983,-20.465) H24(0.068,-20.465) H27(-0.848,-20.465) H29(-1.763,-20.465) H31(-2.678,-20.465)
  oval 0.203x0.305 smd: A34(-4.176,-24.011) A35(-4.795,-24.365) B35(-4.795,-23.715)
  oval 0.305x0.203 smd: AA49(-11.511,-14.246) AB48(-11.215,-13.626) AB49(-11.865,-13.626) AC47(-10.891,-12.995) AC49(-11.541,-12.995) AE48(-11.215,-12.364) AE49(-11.865,-12.364) AF49(-11.511,-11.744) AG48(-11.215,-11.124) AG49(-11.865,-11.124) AH1(11.865,-10.706) AH2(11.215,-10.706) AH47(-10.891,-10.493) AH49(-11.541,-10.493) AJ1(11.865,-10.056) AJ2(11.215,-10.056) AK48(-11.215,-9.862) AK49(-11.865,-9.862) AL1(11.865,-9.406) AL2(11.215,-9.406) AL49(-11.511,-9.242) AM1(11.865,-8.756) AM2(11.215,-8.756) AM48(-11.215,-8.622) AM49(-11.865,-8.622) AN1(11.865,-8.106) AN2(11.215,-8.106) AN47(-10.891,-7.991) AN49(-11.541,-7.991) AR1(11.865,-7.456) AR2(11.215,-7.456) AR48(-11.215,-7.36) AR49(-11.865,-7.36) AT1(11.865,-6.806) AT2(11.215,-6.806) AT49(-11.511,-6.74) AU1(11.865,-6.156) AU2(11.215,-6.156) AU48(-11.215,-6.12) AU49(-11.865,-6.12) AV1(11.865,-5.506) AV2(11.215,-5.506) AV47(-10.891,-5.489) AV49(-11.541,-5.489) AY1(11.865,-4.856) AY2(11.215,-4.856) AY48(-11.215,-4.858) AY49(-11.865,-4.858) BA1(11.865,-4.206) BA2(11.215,-4.206) BA49(-11.511,-4.238) BB1(11.865,-3.556) BB2(11.215,-3.556) BB48(-11.215,-3.618) BB49(-11.865,-3.618) BD1(11.865,-2.906) BD2(11.215,-2.906) BD47(-10.891,-2.987) BD49(-11.541,-2.987) BE1(11.865,-2.256) BE2(11.215,-2.256) BE48(-11.215,-2.356) BE49(-11.865,-2.356) BF1(11.865,-1.606) BF2(11.215,-1.606) BF49(-11.511,-1.736) BG48(-11.215,-1.116) BG49(-11.865,-1.116) BH1(11.865,-0.956) BH2(11.215,-0.956) BJ1(11.865,-0.306) BJ2(11.215,-0.306) BJ47(-10.891,-0.485) BJ49(-11.541,-0.485) BL1(11.865,0.344) BL2(11.215,0.344) BL48(-11.215,0.146) BL49(-11.865,0.146) BM1(11.865,0.994) BM2(11.215,0.994) BM49(-11.511,0.766) BN48(-11.215,1.386) BN49(-11.865,1.386) BP1(11.865,1.644) BP2(11.215,1.644) BR1(11.865,2.294) BR2(11.215,2.294) BR47(-10.891,2.017) BR49(-11.541,2.017) BT1(11.865,2.944) BT2(11.215,2.944) BT48(-11.215,2.648) BT49(-11.865,2.648) BU49(-11.511,3.268) BV1(11.865,3.594) BV2(11.215,3.594) BV48(-11.215,3.888) BV49(-11.865,3.888) BW1(11.865,4.244) BW2(11.215,4.244) BY1(11.865,4.894) BY2(11.215,4.894) BY47(-10.891,4.519) BY49(-11.541,4.519) CA48(-11.215,5.15) CA49(-11.865,5.15) CB1(11.865,5.544) CB2(11.215,5.544) CB49(-11.511,5.77) CC48(-11.215,6.39) CC49(-11.865,6.39) CE47(-10.891,7.021) CE49(-11.541,7.021) CF48(-11.215,7.652) CF49(-11.865,7.652) CG49(-11.511,8.272) CH48(-11.215,8.892) CH49(-11.865,8.892) CK47(-10.891,9.523) CK49(-11.541,9.523) CL48(-11.215,10.154) CL49(-11.865,10.154) CM49(-11.511,10.774) CN48(-11.215,11.394) CN49(-11.865,11.394) CR47(-10.891,12.025) CR49(-11.541,12.025) CT48(-11.215,12.656) CT49(-11.865,12.656) CU49(-11.511,13.276) CV48(-11.215,13.896) CV49(-11.865,13.896) CY47(-10.891,14.527) CY49(-11.541,14.527) DA48(-11.215,15.158) DA49(-11.865,15.158) DB49(-11.511,15.778) DC48(-11.215,16.398) DC49(-11.865,16.398) DE47(-10.891,17.029) DE49(-11.541,17.029) DF48(-11.215,17.66) DF49(-11.865,17.66) T49(-11.511,-16.748) U48(-11.215,-16.128) U49(-11.865,-16.128) V47(-10.891,-15.497) V49(-11.541,-15.497) Y48(-11.215,-14.866) Y49(-11.865,-14.866)
  oval 0.33x0.254 smd: AB1(11.543,-13.923) AC1(11.865,-13.249) AC2(11.215,-13.249) AE1(11.865,-12.123) AE2(11.215,-12.123) AG1(11.543,-11.449) CC1(11.543,6.149) CD1(11.865,6.823) CD2(11.215,6.823) CF1(11.865,7.949) CF2(11.215,7.949) CH1(11.543,8.623) CJ1(11.865,9.297) CJ2(11.215,9.297) CL1(11.865,10.423) CL2(11.215,10.423) CN1(11.543,11.097) CP1(11.865,11.771) CP2(11.215,11.771) CT1(11.865,12.897) CT2(11.215,12.897) CV1(11.543,13.571) CW1(11.865,14.245) CW2(11.215,14.245) DA1(11.865,15.371) DA2(11.215,15.371) DC1(11.543,16.045) DD1(11.865,16.719) DD2(11.215,16.719) DF1(11.865,17.845) DF2(11.215,17.845) DG49(-11.511,18.288) DH1(11.543,18.519) DH48(-11.215,18.871) DH49(-11.865,18.871) DJ1(11.865,19.193) DJ2(11.215,19.193) DK47(-10.89,19.524) DK49(-11.54,19.524) DL1(11.865,20.319) DL2(11.215,20.319) DL48(-11.215,20.177) DL49(-11.865,20.177) DM47(-10.89,20.741) DM49(-11.54,20.741) DN1(11.543,20.993) DN48(-11.215,21.305) DN49(-11.865,21.305) DP2(11.215,21.667) H2(11.215,-20.671) H47(-10.89,-20.641) H49(-11.54,-20.641) J48(-11.215,-19.988) J49(-11.865,-19.988) K1(11.865,-19.545) K2(11.215,-19.545) L49(-11.54,-19.335) M1(11.543,-18.871) M48(-11.215,-18.682) M49(-11.865,-18.682) N1(11.865,-18.197) N2(11.215,-18.197) N47(-10.89,-18.029) N49(-11.54,-18.029) R1(11.865,-17.071) R2(11.215,-17.071) R48(-11.215,-17.376) R49(-11.865,-17.376) U1(11.543,-16.397) V1(11.865,-15.723) V2(11.215,-15.723) Y1(11.865,-14.597) Y2(11.215,-14.597)
C0402
  rect 0.55x0.5 smd: 1(-0.475,0) 2(0.475,0)
CAE630W570HN
  rect 3.5x1.6 smd: 1(-2.85,0) 2(2.85,0)
CAE660W800HN
  rect 3.35x1.6 smd: 1(-2.45,0) 2(2.45,0)
CAE6800W1000HN
  rect 3.3x1.3 smd: 1(-3.025,0) 2(3.025,0)
CC0402N
  rect 0.55x0.5 smd: 1(-0.475,0) 2(0.475,0)
CC0603N
  rect 0.8x0.8 smd: 1(-0.75,0) 2(0.75,0)
CC0805N
  rect 1x1.2 smd: 1(-1,0) 2(1,0)
CC1206N
  rect 1.2x1.6 smd: 1(-1.6,0) 2(1.6,0)
CC1210N
  rect 1.3x2.6 smd: 1(-1.4,0) 2(1.4,0)
CC5750N
  rect 1.4x5 smd: 1(-2.75,0) 2(2.75,0)
CCP7343N
  rect 2.6x2.6 smd: 1(-3.05,0) 2(3.05,0)
DFN50P200X200-8CN
  oval 0.65x0.25 smd: 1(-0.95,0.75) 2(-0.95,0.25) 3(-0.95,-0.25) 4(-0.95,-0.75) 5(0.95,-0.75) 6(0.95,-0.25) 7(0.95,0.25) 8(0.95,0.75)
  rect 0.6x1.3 smd: E1(0,0)
DFN65P280X290-8N
  oval 0.7x0.35 smd: 1(-1.296,0.975) 2(-1.296,0.325) 3(-1.296,-0.325) 4(-1.296,-0.975) 5(1.304,-0.975) 6(1.304,-0.325) 7(1.304,0.325) 8(1.304,0.975)
  rect 1.2x2.3 smd: 9(0.215,-0.05)
DFN2510P10E
  rect 0.25x0.65 smd: 1(-1.001,-0.439) 2(-0.5,-0.439) 4(0.5,-0.439) 5(1.001,-0.439) 6(1.001,0.439) 7(0.5,0.439) 9(-0.5,0.439) 10(-1.001,0.439)
  rect 0.4x1.55 smd: 8(0,0)
F1206N
  rect 1.3x1.8 smd: 1(-1.45,0) 2(1.45,0)
FB0603N
  rect 0.8x0.8 smd: 1(-0.75,0) 2(0.75,0)
FB0805N
  rect 1x1.2 smd: 1(-1,0) 2(1,0)
FIL_175P200X120-4L
  rect 0.6x0.7 smd: 1(-0.5,0.875) 2(-0.5,-0.875) 3(0.5,-0.875) 4(0.5,0.875)
KPAK127P605-9N
  rect 0.9x1.5 smd: (-1.757,1.811)
  rect 0.7x0.5 smd: 1(-2.79,1.905) 3(2.79,-1.905) 4(2.79,-0.635) 5(2.79,0.635) 6(2.79,1.905)
  rect 1.85x3 smd: 2(-2.215,-0.637)
  rect 2.6x4.8 smd: 7(0.47,0.004)
LC3030DL
  rect 1.5x3.2 smd: 1(-1.05,0) 2(1.05,0)
LC4040L
  rect 4.4x1.6 smd: 1(0,1.4) 2(0,-1.4)
LC6666N
  rect 2.3x3.3 smd: 1(-3.075,0) 2(3.075,0)
LC7266N
  rect 3.5x2.6 smd: 1(0,3.15) 2(0,-3.15)
LED1706N
  rect 0.8x0.8 smd: 1(0.85,0) 2(-0.85,0)
LQFP40P1600X1600-128N_A
  oval 1.3x0.2 smd: 1(-7.65,6.2) 2(-7.65,5.8) 3(-7.65,5.4) 4(-7.65,5) 5(-7.65,4.6) 6(-7.65,4.2) 7(-7.65,3.8) 8(-7.65,3.4) 9(-7.65,3) 10(-7.65,2.6) 11(-7.65,2.2) 12(-7.65,1.8) 13(-7.65,1.4) 14(-7.65,1) 15(-7.65,0.6) 16(-7.65,0.2) 17(-7.65,-0.2) 18(-7.65,-0.6) 19(-7.65,-1) 20(-7.65,-1.4) 21(-7.65,-1.8) 22(-7.65,-2.2) 23(-7.65,-2.6) 24(-7.65,-3) 25(-7.65,-3.4) 26(-7.65,-3.8) 27(-7.65,-4.2) 28(-7.65,-4.6) 29(-7.65,-5) 30(-7.65,-5.4) 31(-7.65,-5.8) 32(-7.65,-6.2) 65(7.65,-6.2) 66(7.65,-5.8) 67(7.65,-5.4) 68(7.65,-5) 69(7.65,-4.6) 70(7.65,-4.2) 71(7.65,-3.8) 72(7.65,-3.4) 73(7.65,-3) 74(7.65,-2.6) 75(7.65,-2.2) 76(7.65,-1.8) 77(7.65,-1.4) 78(7.65,-1) 79(7.65,-0.6) 80(7.65,-0.2) 81(7.65,0.2) 82(7.65,0.6) 83(7.65,1) 84(7.65,1.4) 85(7.65,1.8) 86(7.65,2.2) 87(7.65,2.6) 88(7.65,3) 89(7.65,3.4) 90(7.65,3.8) 91(7.65,4.2) 92(7.65,4.6) 93(7.65,5) 94(7.65,5.4) 95(7.65,5.8) 96(7.65,6.2)
  oval 0.2x1.3 smd: 33(-6.2,-7.65) 34(-5.8,-7.65) 35(-5.4,-7.65) 36(-5,-7.65) 37(-4.6,-7.65) 38(-4.2,-7.65) 39(-3.8,-7.65) 40(-3.4,-7.65) 41(-3,-7.65) 42(-2.6,-7.65) 43(-2.2,-7.65) 44(-1.8,-7.65) 45(-1.4,-7.65) 46(-1,-7.65) 47(-0.6,-7.65) 48(-0.2,-7.65) 49(0.2,-7.65) 50(0.6,-7.65) 51(1,-7.65) 52(1.4,-7.65) 53(1.8,-7.65) 54(2.2,-7.65) 55(2.6,-7.65) 56(3,-7.65) 57(3.4,-7.65) 58(3.8,-7.65) 59(4.2,-7.65) 60(4.6,-7.65) 61(5,-7.65) 62(5.4,-7.65) 63(5.8,-7.65) 64(6.2,-7.65) 97(6.2,7.65) 98(5.8,7.65) 99(5.4,7.65) 100(5,7.65) 101(4.6,7.65) 102(4.2,7.65) 103(3.8,7.65) 104(3.4,7.65) 105(3,7.65) 106(2.6,7.65) 107(2.2,7.65) 108(1.8,7.65) 109(1.4,7.65) 110(1,7.65) 111(0.6,7.65) 112(0.2,7.65) 113(-0.2,7.65) 114(-0.6,7.65) 115(-1,7.65) 116(-1.4,7.65) 117(-1.8,7.65) 118(-2.2,7.65) 119(-2.6,7.65) 120(-3,7.65) 121(-3.4,7.65) 122(-3.8,7.65) 123(-4.2,7.65) 124(-4.6,7.65) 125(-5,7.65) 126(-5.4,7.65) 127(-5.8,7.65) 128(-6.2,7.65)
MARK-D100D250
  round 1 smd: 1(0,0)
MTG220H400
  round 4 hole 2.2: 1(0,0)
MTG230H500
  round 5 hole 2.3: 1(0,0)
MTG340H580_TOP
  round 5.8 hole 3.4: 1(0,0)
MTG380H500
  round 5 hole 3.8: 1(0,0)
MTG380H600
  round 6 hole 3.8: 1(0,0)
NET_SHORT
  round 0.55 hole 0.25: 1(0,0)
  round 0.127 smd: 2(0.2,0)
OSC170P320X250-4N
  rect 1.4x1.15 smd: 1(-1.1,-0.85) 2(1.1,-0.85) 3(1.1,0.85) 4(-1.1,0.85)
QFN40P300X300-20N
  oval 0.6x0.2 smd: 1(-1.4,0.8) 2(-1.4,0.4) 3(-1.4,0) 4(-1.4,-0.4) 5(-1.4,-0.8) 11(1.4,-0.8) 12(1.4,-0.4) 13(1.4,0) 14(1.4,0.4) 15(1.4,0.8)
  oval 0.2x0.6 smd: 6(-0.8,-1.4) 7(-0.4,-1.4) 8(0,-1.4) 9(0.4,-1.4) 10(0.8,-1.4) 16(0.8,1.4) 17(0.4,1.4) 18(0,1.4) 19(-0.4,1.4) 20(-0.8,1.4)
  rect 1.8x1.8 smd: E1(0,0)
QFN40P300X300-20N_A
  oval 0.85x0.2 smd: 1(-1.475,0.8) 2(-1.475,0.4) 3(-1.475,0) 4(-1.475,-0.4) 5(-1.475,-0.8) 11(1.475,-0.8) 12(1.475,-0.4) 13(1.475,0) 14(1.475,0.4) 15(1.475,0.8)
  oval 0.2x0.85 smd: 6(-0.8,-1.475) 7(-0.4,-1.475) 8(0,-1.475) 9(0.4,-1.475) 10(0.8,-1.475) 16(0.8,1.475) 17(0.4,1.475) 18(0,1.475) 19(-0.4,1.475) 20(-0.8,1.475)
  rect 1.7x1.7 smd: E1(0,0)
QFN40P400X400-32AN
  oval 0.8x0.2 smd: 1(-2,1.4) 2(-2,1) 3(-2,0.6) 4(-2,0.2) 5(-2,-0.2) 6(-2,-0.6) 7(-2,-1) 8(-2,-1.4) 17(2,-1.4) 18(2,-1) 19(2,-0.6) 20(2,-0.2) 21(2,0.2) 22(2,0.6) 23(2,1) 24(2,1.4)
  oval 0.2x0.8 smd: 9(-1.4,-2) 10(-1,-2) 11(-0.6,-2) 12(-0.2,-2) 13(0.2,-2) 14(0.6,-2) 15(1,-2) 16(1.4,-2) 25(1.4,2) 26(1,2) 27(0.6,2) 28(0.2,2) 29(-0.2,2) 30(-0.6,2) 31(-1,2) 32(-1.4,2)
  rect 2.7x2.7 smd: E1(0,0)
QFN40P500X500-40N_B
  oval 0.85x0.2 smd: 1(-2.475,1.8) 2(-2.475,1.4) 3(-2.475,1) 4(-2.475,0.6) 5(-2.475,0.2) 6(-2.475,-0.2) 7(-2.475,-0.6) 8(-2.475,-1) 9(-2.475,-1.4) 10(-2.475,-1.8) 21(2.475,-1.8) 22(2.475,-1.4) 23(2.475,-1) 24(2.475,-0.6) 25(2.475,-0.2) 26(2.475,0.2) 27(2.475,0.6) 28(2.475,1) 29(2.475,1.4) 30(2.475,1.8)
  oval 0.2x0.85 smd: 11(-1.8,-2.475) 12(-1.4,-2.475) 13(-1,-2.475) 14(-0.6,-2.475) 15(-0.2,-2.475) 16(0.2,-2.475) 17(0.6,-2.475) 18(1,-2.475) 19(1.4,-2.475) 20(1.8,-2.475) 31(1.8,2.475) 32(1.4,2.475) 33(1,2.475) 34(0.6,2.475) 35(0.2,2.475) 36(-0.2,2.475) 37(-0.6,2.475) 38(-1,2.475) 39(-1.4,2.475) 40(-1.8,2.475)
  rect 3.4x3.4 smd: E1(0,0)
QFN40P600X600-48N
  oval 0.7x0.2 smd: 1(-2.9,2.2) 2(-2.9,1.8) 3(-2.9,1.4) 4(-2.9,1) 5(-2.9,0.6) 6(-2.9,0.2) 7(-2.9,-0.2) 8(-2.9,-0.6) 9(-2.9,-1) 10(-2.9,-1.4) 11(-2.9,-1.8) 12(-2.9,-2.2) 25(2.9,-2.2) 26(2.9,-1.8) 27(2.9,-1.4) 28(2.9,-1) 29(2.9,-0.6) 30(2.9,-0.2) 31(2.9,0.2) 32(2.9,0.6) 33(2.9,1) 34(2.9,1.4) 35(2.9,1.8) 36(2.9,2.2)
  oval 0.2x0.7 smd: 13(-2.2,-2.9) 14(-1.8,-2.9) 15(-1.4,-2.9) 16(-1,-2.9) 17(-0.6,-2.9) 18(-0.2,-2.9) 19(0.2,-2.9) 20(0.6,-2.9) 21(1,-2.9) 22(1.4,-2.9) 23(1.8,-2.9) 24(2.2,-2.9) 37(2.2,2.9) 38(1.8,2.9) 39(1.4,2.9) 40(1,2.9) 41(0.6,2.9) 42(0.2,2.9) 43(-0.2,2.9) 44(-0.6,2.9) 45(-1,2.9) 46(-1.4,2.9) 47(-1.8,2.9) 48(-2.2,2.9)
  rect 4.3x4.3 smd: E1(0,0)
QFN40P700X700-56AN
  oval 0.7x0.2 smd: 1(-3.4,2.6) 2(-3.4,2.2) 3(-3.4,1.8) 4(-3.4,1.4) 5(-3.4,1) 6(-3.4,0.6) 7(-3.4,0.2) 8(-3.4,-0.2) 9(-3.4,-0.6) 10(-3.4,-1) 11(-3.4,-1.4) 12(-3.4,-1.8) 13(-3.4,-2.2) 14(-3.4,-2.6) 29(3.4,-2.6) 30(3.4,-2.2) 31(3.4,-1.8) 32(3.4,-1.4) 33(3.4,-1) 34(3.4,-0.6) 35(3.4,-0.2) 36(3.4,0.2) 37(3.4,0.6) 38(3.4,1) 39(3.4,1.4) 40(3.4,1.8) 41(3.4,2.2) 42(3.4,2.6)
  oval 0.2x0.7 smd: 15(-2.6,-3.4) 16(-2.2,-3.4) 17(-1.8,-3.4) 18(-1.4,-3.4) 19(-1,-3.4) 20(-0.6,-3.4) 21(-0.2,-3.4) 22(0.2,-3.4) 23(0.6,-3.4) 24(1,-3.4) 25(1.4,-3.4) 26(1.8,-3.4) 27(2.2,-3.4) 28(2.6,-3.4) 43(2.6,3.4) 44(2.2,3.4) 45(1.8,3.4) 46(1.4,3.4) 47(1,3.4) 48(0.6,3.4) 49(0.2,3.4) 50(-0.2,3.4) 51(-0.6,3.4) 52(-1,3.4) 53(-1.4,3.4) 54(-1.8,3.4) 55(-2.2,3.4) 56(-2.6,3.4)
  rect 4.1x4.8 smd: E1(0,0)
QFN72P300X300-20N
  oval 0.7x0.23 smd: 1(-1.4,0.62) 6(1.4,0.62)
  oval 1.35x0.23 smd: 2(-1.18,-0.1) 3(-1.18,-1)
  oval 2.1x0.23 smd: 4(0.72,-0.55) 5(0.72,0.17)
  oval 0.23x0.7 smd: 7(1.125,1.4) 8(0.675,1.4) 9(0.225,1.4) 10(-0.225,1.4) 11(-0.675,1.4) 12(-1.125,1.4)
R0402
  rect 0.508x0.508 smd: 1(-0.445,0) 2(0.445,0)
RC0402L
  custom 0.125x0.125 smd: 1(-0.45,0) 2(0.45,0)
RC0402N
  rect 0.55x0.5 smd: 1(-0.475,0) 2(0.475,0)
RC0603N
  rect 0.8x0.8 smd: 1(-0.75,0) 2(0.75,0)
RC0805N
  rect 1x1.2 smd: 1(-1,0) 2(1,0)
RC1206N
  rect 1.2x1.6 smd: 1(-1.6,0) 2(1.6,0)
RC2512N
  rect 1.65x3.68 smd: 1(-2.855,0) 2(2.855,0)
SFB1206A
  rect 1.016x1.524 smd: 1(-1.397,0) 2(1.397,0)
SHDR1X3_254-HB11031
  round 1.801 hole 1.001: 1(0,0) 2(2.54,0) 3(5.08,0)
SKSOP8_127-1140X920
  rect 0.508x1.524 smd: 1(1.905,4) 2(0.635,4) 3(-0.635,4) 4(-1.905,4) 5(-1.905,-4) 6(-0.635,-4) 7(0.635,-4) 8(1.905,-4)
SMD-BATTERY-2900P-2N
  rect 3x4.2 smd: 1(14.5,0) 2(-14.5,0)
SMD-CN-50P-10N-H
  oval 0.28x1.25 smd: 1(-1,2.325) 2(-0.5,2.325) 3(0,2.325) 4(0.5,2.325) 5(1,2.325) 6(1.5,2.325) 7(2,2.325) 8(2.5,2.325) 9(3,2.325) 10(3.5,2.325)
  rect 2x3 smd: E1(-2.69,0) E2(5.19,0)
SMD-CN-80X820P-52DN-RN
  round 1.1 hole 1.1 unplated: (-18.7,0)
  round 1.6 hole 1.6 unplated: (6.3,0)
  rect 0.5x2 smd: 1(5.6,4.1) 2(5.2,-4.1) 3(4.8,4.1) 4(4.4,-4.1) 5(4,4.1) 6(3.6,-4.1) 7(3.2,4.1) 8(2.8,-4.1) 9(2.4,4.1) 10(2,-4.1) 11(1.6,4.1) 12(1.2,-4.1) 13(0.8,4.1) 14(0.4,-4.1) 15(0,4.1) 16(-0.4,-4.1) 17(-4,4.1) 18(-4.4,-4.1) 19(-4.8,4.1) 20(-5.2,-4.1) 21(-5.6,4.1) 22(-6,-4.1) 23(-6.4,4.1) 24(-6.8,-4.1) 25(-7.2,4.1) 26(-7.6,-4.1) 27(-8,4.1) 28(-8.4,-4.1) 29(-8.8,4.1) 30(-9.2,-4.1) 31(-9.6,4.1) 32(-10,-4.1) 33(-10.4,4.1) 34(-10.8,-4.1) 35(-11.2,4.1) 36(-11.6,-4.1) 37(-12,4.1) 38(-12.4,-4.1) 39(-12.8,4.1) 40(-13.2,-4.1) 41(-13.6,4.1) 42(-14,-4.1) 43(-14.4,4.1) 44(-14.8,-4.1) 45(-15.2,4.1) 46(-15.6,-4.1) 47(-16,4.1) 48(-16.4,-4.1) 49(-16.8,4.1) 50(-17.2,-4.1) 51(-17.6,4.1) 52(-18,-4.1)
  rect 2.3x3.2 smd: E1(-20.85,3.5) E2(8.45,3.5)
SMD-CN-100P-2N-V-CB
  rect 0.6x1.5 smd: 1(0.5,2.55) 2(-0.5,2.55)
  rect 1.2x1.8 smd: E1(-1.8,0) E2(1.8,0)
SMD-CN-100P-4N-V-CB
  rect 0.6x1.5 smd: 1(1.5,2.55) 2(0.5,2.55) 3(-0.5,2.55) 4(-1.5,2.55)
  rect 1.2x1.8 smd: E1(-2.8,0) E2(2.8,0)
SMD-CN-100P-40AN-H
  rect 0.6x1.6 smd: 1(-9.5,-2.9) 2(-8.5,-2.9) 3(-7.5,-2.9) 4(-6.5,-2.9) 5(-5.5,-2.9) 6(-4.5,-2.9) 7(-3.5,-2.9) 8(-2.5,-2.9) 9(-1.5,-2.9) 10(-0.5,-2.9) 11(0.5,-2.9) 12(1.5,-2.9) 13(2.5,-2.9) 14(3.5,-2.9) 15(4.5,-2.9) 16(5.5,-2.9) 17(6.5,-2.9) 18(7.5,-2.9) 19(8.5,-2.9) 20(9.5,-2.9) 21(9.5,2.9) 22(8.5,2.9) 23(7.5,2.9) 24(6.5,2.9) 25(5.5,2.9) 26(4.5,2.9) 27(3.5,2.9) 28(2.5,2.9) 29(1.5,2.9) 30(0.5,2.9) 31(-0.5,2.9) 32(-1.5,2.9) 33(-2.5,2.9) 34(-3.5,2.9) 35(-4.5,2.9) 36(-5.5,2.9) 37(-6.5,2.9) 38(-7.5,2.9) 39(-8.5,2.9) 40(-9.5,2.9)
  rect 1.5x2.3 smd: E1(-11.5,-1.3) E2(11.5,-1.3)
SMD-CN-125P-2WBN
  rect 0.8x1.5 smd: 1(-0.625,2.49) 2(0.625,2.49)
  rect 2x2.5 smd: E1(-3.175,0) E2(3.175,0)
SMD-CN-200P-2N-H
  rect 1x3.5 smd: 1(-1,0) 2(1,0)
  rect 1.5x3.4 smd: E1(-3.35,-5.75) E2(3.35,-5.75)
SMD-CN-200P-8N
  rect 1x3 smd: 1(-3,-2.25) 2(-3,2.25) 3(-1,-2.25) 4(-1,2.25) 5(1,-2.25) 6(1,2.25) 7(3,-2.25) 8(3,2.25)
SMD-DDR4-50X820P-260N-9L
  round 1.1 hole 1.1 unplated: (-34.4,0)
  round 1.6 hole 1.6 unplated: (34.4,0)
  rect 0.28x2 smd: 1(33.375,4.1) 2(33.125,-4.1) 3(32.875,4.1) 4(32.625,-4.1) 5(32.375,4.1) 6(32.125,-4.1) 7(31.875,4.1) 8(31.625,-4.1) 9(31.375,4.1) 10(31.125,-4.1) 11(30.875,4.1) 12(30.625,-4.1) 13(30.375,4.1) 14(30.125,-4.1) 15(29.875,4.1) 16(29.625,-4.1) 17(29.375,4.1) 18(29.125,-4.1) 19(28.875,4.1) 20(28.625,-4.1) 21(28.375,4.1) 22(28.125,-4.1) 23(27.875,4.1) 24(27.625,-4.1) 25(27.375,4.1) 26(27.125,-4.1) 27(26.875,4.1) 28(26.625,-4.1) 29(26.375,4.1) 30(26.125,-4.1) 31(25.875,4.1) 32(25.625,-4.1) 33(25.375,4.1) 34(25.125,-4.1) 35(24.875,4.1) 36(24.625,-4.1) 37(24.375,4.1) 38(24.125,-4.1) 39(23.875,4.1) 40(23.625,-4.1) 41(23.375,4.1) 42(23.125,-4.1) 43(22.875,4.1) 44(22.625,-4.1) 45(22.375,4.1) 46(22.125,-4.1) 47(21.875,4.1) 48(21.625,-4.1) 49(21.375,4.1) 50(21.125,-4.1) 51(20.875,4.1) 52(20.625,-4.1) 53(20.375,4.1) 54(20.125,-4.1) 55(19.875,4.1) 56(19.625,-4.1) 57(19.375,4.1) 58(19.125,-4.1) 59(18.875,4.1) 60(18.625,-4.1) 61(18.375,4.1) 62(18.125,-4.1) 63(17.875,4.1) 64(17.625,-4.1) 65(17.375,4.1) 66(17.125,-4.1) 67(16.875,4.1) 68(16.625,-4.1) 69(16.375,4.1) 70(16.125,-4.1) 71(15.875,4.1) 72(15.625,-4.1) 73(15.375,4.1) 74(15.125,-4.1) 75(14.875,4.1) 76(14.625,-4.1) 77(14.375,4.1) 78(14.125,-4.1) 79(13.875,4.1) 80(13.625,-4.1) 81(13.375,4.1) 82(13.125,-4.1) 83(12.875,4.1) 84(12.625,-4.1) 85(12.375,4.1) 86(12.125,-4.1) 87(11.875,4.1) 88(11.625,-4.1) 89(11.375,4.1) 90(11.125,-4.1) 91(10.875,4.1) 92(10.625,-4.1) 93(10.375,4.1) 94(10.125,-4.1) 95(9.875,4.1) 96(9.625,-4.1) 97(9.375,4.1) 98(9.125,-4.1) 99(8.875,4.1) 100(8.625,-4.1) 101(8.375,4.1) 102(8.125,-4.1) 103(7.875,4.1) 104(7.625,-4.1) 105(7.375,4.1) 106(7.125,-4.1) 107(6.875,4.1) 108(6.625,-4.1) 109(6.375,4.1) 110(6.125,-4.1) 111(5.875,4.1) 112(5.625,-4.1) 113(5.375,4.1) 114(5.125,-4.1) 115(4.875,4.1) 116(4.625,-4.1) 117(4.375,4.1) 118(4.125,-4.1) 119(3.875,4.1) 120(3.625,-4.1) 121(3.375,4.1) 122(3.125,-4.1) 123(2.875,4.1) 124(2.625,-4.1) 125(2.375,4.1) 126(2.125,-4.1) 127(1.875,4.1) 128(1.625,-4.1) 129(1.375,4.1) 130(1.125,-4.1) 131(0.875,4.1) 132(0.625,-4.1) 133(0.375,4.1) 134(0.125,-4.1) 135(-0.125,4.1) 136(-0.375,-4.1) 137(-0.625,4.1) 138(-0.875,-4.1) 139(-1.125,4.1) 140(-1.375,-4.1) 141(-1.625,4.1) 142(-1.875,-4.1) 143(-2.125,4.1) 144(-2.375,-4.1) 145(-4.625,4.1) 146(-4.875,-4.1) 147(-5.125,4.1) 148(-5.375,-4.1) 149(-5.625,4.1) 150(-5.875,-4.1) 151(-6.125,4.1) 152(-6.375,-4.1) 153(-6.625,4.1) 154(-6.875,-4.1) 155(-7.125,4.1) 156(-7.375,-4.1) 157(-7.625,4.1) 158(-7.875,-4.1) 159(-8.125,4.1) 160(-8.375,-4.1) 161(-8.625,4.1) 162(-8.875,-4.1) 163(-9.125,4.1) 164(-9.375,-4.1) 165(-9.625,4.1) 166(-9.875,-4.1) 167(-10.125,4.1) 168(-10.375,-4.1) 169(-10.625,4.1) 170(-10.875,-4.1) 171(-11.125,4.1) 172(-11.375,-4.1) 173(-11.625,4.1) 174(-11.875,-4.1) 175(-12.125,4.1) 176(-12.375,-4.1) 177(-12.625,4.1) 178(-12.875,-4.1) 179(-13.125,4.1) 180(-13.375,-4.1) 181(-13.625,4.1) 182(-13.875,-4.1) 183(-14.125,4.1) 184(-14.375,-4.1) 185(-14.625,4.1) 186(-14.875,-4.1) 187(-15.125,4.1) 188(-15.375,-4.1) 189(-15.625,4.1) 190(-15.875,-4.1) 191(-16.125,4.1) 192(-16.375,-4.1) 193(-16.625,4.1) 194(-16.875,-4.1) 195(-17.125,4.1) 196(-17.375,-4.1) 197(-17.625,4.1) 198(-17.875,-4.1) 199(-18.125,4.1) 200(-18.375,-4.1) 201(-18.625,4.1) 202(-18.875,-4.1) 203(-19.125,4.1) 204(-19.375,-4.1) 205(-19.625,4.1) 206(-19.875,-4.1) 207(-20.125,4.1) 208(-20.375,-4.1) 209(-20.625,4.1) 210(-20.875,-4.1) 211(-21.125,4.1) 212(-21.375,-4.1) 213(-21.625,4.1) 214(-21.875,-4.1) 215(-22.125,4.1) 216(-22.375,-4.1) 217(-22.625,4.1) 218(-22.875,-4.1) 219(-23.125,4.1) 220(-23.375,-4.1) 221(-23.625,4.1) 222(-23.875,-4.1) 223(-24.125,4.1) 224(-24.375,-4.1) 225(-24.625,4.1) 226(-24.875,-4.1) 227(-25.125,4.1) 228(-25.375,-4.1) 229(-25.625,4.1) 230(-25.875,-4.1) 231(-26.125,4.1) 232(-26.375,-4.1) 233(-26.625,4.1) 234(-26.875,-4.1) 235(-27.125,4.1) 236(-27.375,-4.1) 237(-27.625,4.1) 238(-27.875,-4.1) 239(-28.125,4.1) 240(-28.375,-4.1) 241(-28.625,4.1) 242(-28.875,-4.1) 243(-29.125,4.1) 244(-29.375,-4.1) 245(-29.625,4.1) 246(-29.875,-4.1) 247(-30.125,4.1) 248(-30.375,-4.1) 249(-30.625,4.1) 250(-30.875,-4.1) 251(-31.125,4.1) 252(-31.375,-4.1) 253(-31.625,4.1) 254(-31.875,-4.1) 255(-32.125,4.1) 256(-32.375,-4.1) 257(-32.625,4.1) 258(-32.875,-4.1) 259(-33.125,4.1) 260(-33.375,-4.1)
  rect 2.6x4.2 smd: E1(-37.75,-8) E2(37.75,-12)
SMD-DDR4-50X820P-260N-L
  round 1.1 hole 1.1 unplated: (-34.4,0)
  round 1.6 hole 1.6 unplated: (34.4,0)
  rect 0.28x2 smd: 1(33.375,4.1) 2(33.125,-4.1) 3(32.875,4.1) 4(32.625,-4.1) 5(32.375,4.1) 6(32.125,-4.1) 7(31.875,4.1) 8(31.625,-4.1) 9(31.375,4.1) 10(31.125,-4.1) 11(30.875,4.1) 12(30.625,-4.1) 13(30.375,4.1) 14(30.125,-4.1) 15(29.875,4.1) 16(29.625,-4.1) 17(29.375,4.1) 18(29.125,-4.1) 19(28.875,4.1) 20(28.625,-4.1) 21(28.375,4.1) 22(28.125,-4.1) 23(27.875,4.1) 24(27.625,-4.1) 25(27.375,4.1) 26(27.125,-4.1) 27(26.875,4.1) 28(26.625,-4.1) 29(26.375,4.1) 30(26.125,-4.1) 31(25.875,4.1) 32(25.625,-4.1) 33(25.375,4.1) 34(25.125,-4.1) 35(24.875,4.1) 36(24.625,-4.1) 37(24.375,4.1) 38(24.125,-4.1) 39(23.875,4.1) 40(23.625,-4.1) 41(23.375,4.1) 42(23.125,-4.1) 43(22.875,4.1) 44(22.625,-4.1) 45(22.375,4.1) 46(22.125,-4.1) 47(21.875,4.1) 48(21.625,-4.1) 49(21.375,4.1) 50(21.125,-4.1) 51(20.875,4.1) 52(20.625,-4.1) 53(20.375,4.1) 54(20.125,-4.1) 55(19.875,4.1) 56(19.625,-4.1) 57(19.375,4.1) 58(19.125,-4.1) 59(18.875,4.1) 60(18.625,-4.1) 61(18.375,4.1) 62(18.125,-4.1) 63(17.875,4.1) 64(17.625,-4.1) 65(17.375,4.1) 66(17.125,-4.1) 67(16.875,4.1) 68(16.625,-4.1) 69(16.375,4.1) 70(16.125,-4.1) 71(15.875,4.1) 72(15.625,-4.1) 73(15.375,4.1) 74(15.125,-4.1) 75(14.875,4.1) 76(14.625,-4.1) 77(14.375,4.1) 78(14.125,-4.1) 79(13.875,4.1) 80(13.625,-4.1) 81(13.375,4.1) 82(13.125,-4.1) 83(12.875,4.1) 84(12.625,-4.1) 85(12.375,4.1) 86(12.125,-4.1) 87(11.875,4.1) 88(11.625,-4.1) 89(11.375,4.1) 90(11.125,-4.1) 91(10.875,4.1) 92(10.625,-4.1) 93(10.375,4.1) 94(10.125,-4.1) 95(9.875,4.1) 96(9.625,-4.1) 97(9.375,4.1) 98(9.125,-4.1) 99(8.875,4.1) 100(8.625,-4.1) 101(8.375,4.1) 102(8.125,-4.1) 103(7.875,4.1) 104(7.625,-4.1) 105(7.375,4.1) 106(7.125,-4.1) 107(6.875,4.1) 108(6.625,-4.1) 109(6.375,4.1) 110(6.125,-4.1) 111(5.875,4.1) 112(5.625,-4.1) 113(5.375,4.1) 114(5.125,-4.1) 115(4.875,4.1) 116(4.625,-4.1) 117(4.375,4.1) 118(4.125,-4.1) 119(3.875,4.1) 120(3.625,-4.1) 121(3.375,4.1) 122(3.125,-4.1) 123(2.875,4.1) 124(2.625,-4.1) 125(2.375,4.1) 126(2.125,-4.1) 127(1.875,4.1) 128(1.625,-4.1) 129(1.375,4.1) 130(1.125,-4.1) 131(0.875,4.1) 132(0.625,-4.1) 133(0.375,4.1) 134(0.125,-4.1) 135(-0.125,4.1) 136(-0.375,-4.1) 137(-0.625,4.1) 138(-0.875,-4.1) 139(-1.125,4.1) 140(-1.375,-4.1) 141(-1.625,4.1) 142(-1.875,-4.1) 143(-2.125,4.1) 144(-2.375,-4.1) 145(-4.625,4.1) 146(-4.875,-4.1) 147(-5.125,4.1) 148(-5.375,-4.1) 149(-5.625,4.1) 150(-5.875,-4.1) 151(-6.125,4.1) 152(-6.375,-4.1) 153(-6.625,4.1) 154(-6.875,-4.1) 155(-7.125,4.1) 156(-7.375,-4.1) 157(-7.625,4.1) 158(-7.875,-4.1) 159(-8.125,4.1) 160(-8.375,-4.1) 161(-8.625,4.1) 162(-8.875,-4.1) 163(-9.125,4.1) 164(-9.375,-4.1) 165(-9.625,4.1) 166(-9.875,-4.1) 167(-10.125,4.1) 168(-10.375,-4.1) 169(-10.625,4.1) 170(-10.875,-4.1) 171(-11.125,4.1) 172(-11.375,-4.1) 173(-11.625,4.1) 174(-11.875,-4.1) 175(-12.125,4.1) 176(-12.375,-4.1) 177(-12.625,4.1) 178(-12.875,-4.1) 179(-13.125,4.1) 180(-13.375,-4.1) 181(-13.625,4.1) 182(-13.875,-4.1) 183(-14.125,4.1) 184(-14.375,-4.1) 185(-14.625,4.1) 186(-14.875,-4.1) 187(-15.125,4.1) 188(-15.375,-4.1) 189(-15.625,4.1) 190(-15.875,-4.1) 191(-16.125,4.1) 192(-16.375,-4.1) 193(-16.625,4.1) 194(-16.875,-4.1) 195(-17.125,4.1) 196(-17.375,-4.1) 197(-17.625,4.1) 198(-17.875,-4.1) 199(-18.125,4.1) 200(-18.375,-4.1) 201(-18.625,4.1) 202(-18.875,-4.1) 203(-19.125,4.1) 204(-19.375,-4.1) 205(-19.625,4.1) 206(-19.875,-4.1) 207(-20.125,4.1) 208(-20.375,-4.1) 209(-20.625,4.1) 210(-20.875,-4.1) 211(-21.125,4.1) 212(-21.375,-4.1) 213(-21.625,4.1) 214(-21.875,-4.1) 215(-22.125,4.1) 216(-22.375,-4.1) 217(-22.625,4.1) 218(-22.875,-4.1) 219(-23.125,4.1) 220(-23.375,-4.1) 221(-23.625,4.1) 222(-23.875,-4.1) 223(-24.125,4.1) 224(-24.375,-4.1) 225(-24.625,4.1) 226(-24.875,-4.1) 227(-25.125,4.1) 228(-25.375,-4.1) 229(-25.625,4.1) 230(-25.875,-4.1) 231(-26.125,4.1) 232(-26.375,-4.1) 233(-26.625,4.1) 234(-26.875,-4.1) 235(-27.125,4.1) 236(-27.375,-4.1) 237(-27.625,4.1) 238(-27.875,-4.1) 239(-28.125,4.1) 240(-28.375,-4.1) 241(-28.625,4.1) 242(-28.875,-4.1) 243(-29.125,4.1) 244(-29.375,-4.1) 245(-29.625,4.1) 246(-29.875,-4.1) 247(-30.125,4.1) 248(-30.375,-4.1) 249(-30.625,4.1) 250(-30.875,-4.1) 251(-31.125,4.1) 252(-31.375,-4.1) 253(-31.625,4.1) 254(-31.875,-4.1) 255(-32.125,4.1) 256(-32.375,-4.1) 257(-32.625,4.1) 258(-32.875,-4.1) 259(-33.125,4.1) 260(-33.375,-4.1)
  rect 3.6x4.6 smd: E1(-33.8,-12) E2(33.8,-12)
